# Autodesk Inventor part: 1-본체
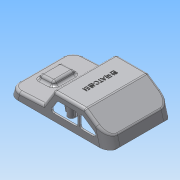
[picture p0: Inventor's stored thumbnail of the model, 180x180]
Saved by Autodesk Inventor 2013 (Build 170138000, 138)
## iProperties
Created: 2015-05
Part Number: 1-본체
Material: ABS 플라스틱
Document SubType Name: Modeling
Designer: Administrator
Density: 7.85 g/cm^3
Mass: 279.283 g
Surface Area: 339.779 cm^2
Volume: 35.5774 cm^3
Author: Administrator
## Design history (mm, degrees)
sketch "스케치1"
  geometry: L1 (-61, -38)-(61, -38); L2 (61, -38)-(61, 38); L3 (61, 38)-(-61, 38); L4 (-61, 38)-(-61, -38); L5 (-61, -38)-(61, 38); L6 (61, -38)-(-61, 38); 1 further point
  constraints: 12 end point, 2 midpoint, 2 parallel, 1 horizontal, 1 perpendicular
  dimensions: "d0" = 122 distance of L2.end L3.end; "d2" = 76 distance of L1.end L2.end
extrude "돌출1" new body sketch "스케치1" distance "d3" = 31; taper "d4" = 0 deg
sketch "스케치2"
  geometry: L1 (0, 0)-(122, 0) reference; L2 (122, 0)-(122, 31) reference; L3 (0, 31)-(122, 31) reference; L4 (0, 0)-(0, 31) reference; L5 (0, 1)-(2.144, 9); L6 (2.144, 9)-(42, 11.089); L7 (92, 31)-(118.833, 12.819); L8 (118.833, 12.819)-(122, 1); L9 (0, 1)-(1, 1); L10 (1, 1)-(1, 0); L11 (122, 1)-(121, 1); L12 (121, 1)-(121, 0); L13 (42, 11.089)-(54.442, 31); L14 (118.833, 12.819)-(122, 11); 1 further point
  constraints: 20 end point, 7 point on line, 4 perpendicular
  dimensions: "d5" = 1 distance of L5.start L9.end; "d7" = 1 distance of L9.end L10.end; "d8" = 105 deg angle of L5 L1; "d9" = 105 deg angle of L8 L1; "d10" = 20 vertical distance of L7.start L14.end; "d11" = 30 horizontal distance of L14.end L7.start; "d12" = 125 deg angle of L13 L6; "d13" = 42 horizontal distance of L6.end L5.start; "d14" = 1 distance of L8.end L11.end; "d15" = 1 distance of L11.end L12.end; "d17" = 9 distance from line of L5.end L1; "d18" = 3 deg angle of L1 L6; "d19" = 60.132 deg angle of L14 L2
extrude "돌출2" sketch "스케치2" distance "d20" = 137.5; taper "d21" = 0 deg
sketch "스케치3"
  geometry: L1 (50, 9.464)-(48.444, 14.553); L2 (48.444, 14.553)-(32.079, 15.41); L3 (32.079, 15.41)-(30, 10.512); L4 (58.856, 9)-(19, 11.089) reference; L5 (61, 1)-(58.856, 9) reference; L6 (60, 0)-(-60, 0) reference; L7 (60, 1)-(61, 1) reference; 2 further points
  constraints: 6 end point, 2 point on line, 1 coincident, 1 parallel
  dimensions: "d25" = 70 deg angle of L3 L4; "d26" = 70 deg angle of L4 L1; "d27" = 11 horizontal distance of point (61, 1) L1.start; "d29" = 20 horizontal distance of L3.end L1.start; "d102" = 5 distance between parallel lines of L2 L4
extrude "돌출3" join sketch "스케치3" stored distance "d30" = 26; taper "d31" = 0 deg
fillet "모깎기1" dims "d32" = 12
fillet "모깎기2" dims "d33" = 3
fillet "모깎기3" dims "d34" = 3
fillet "모깎기4" dims "d35" = 3
feature "쉘1" dims "d36" = 2
sketch "스케치4"
  geometry: L1 (61, 26)-(61, -26) reference; 2 further points
  constraints: 1 horizontal alignment, 1 other
  dimensions: "d37" = 50 distance from line of L1 point (11, 0)
feature "엠보싱1" sketch "스케치4" dims "d5" = 1, "d7" = 1, "d8" = 105 deg, "d9" = 105 deg, "d10" = 20, "d11" = 30, "d12" = 125 deg, "d13" = 42, "d14" = 1, "d15" = 1, "d17" = 9, "d18" = 3 deg, "d19" = 10.49502, "d38" = 0.5, "d39" = 0
sketch "스케치6"
  geometry: L1 (78.924, 28)-(92.685, 18.676) reference; L2 (43.949, 28)-(78.924, 28) reference; L3 (31.561, 8.175)-(43.949, 28) reference; L4 (45.84, 21.59)-(40.216, 12.59); L5 (42.76, 8)-(68.348, 8); L6 (71.348, 11)-(71.348, 20); L7 (68.348, 23)-(48.384, 23); L8 (73.528, 20)-(73.528, 11); L9 (76.528, 8)-(89.752, 8); L10 (76.528, 23)-(77.39, 23); L11 (77.39, 23)-(91.435, 13.484); A1 r 3 centre (42.76, 11) between (40.216, 12.59) and (42.76, 8); A2 r 3 centre (48.384, 20) between (48.384, 23) and (45.84, 21.59); A3 r 3 centre (68.348, 20) between (71.348, 20) and (68.348, 23); A4 r 3 centre (68.348, 11) between (68.348, 8) and (71.348, 11); A5 r 3 centre (89.752, 11) between (89.752, 8) and (91.435, 13.484); A6 r 3 centre (76.528, 11) between (73.528, 11) and (76.528, 8); A7 r 3 centre (76.528, 20) between (76.528, 23) and (73.528, 20); 7 further points
  constraints: 16 end point, 14 point on circle, 14 tangent, 12 point on line, 7 centre point, 5 equal radius, 4 parallel, 4 perpendicular
  dimensions: "d88" = 15 distance of point (71.348, 8) point (71.348, 23); "d90" = 34 distance of point (37.348, 8) point (71.348, 8); "d91" = 5 distance between parallel lines of L3 L4; "d92" = 5 distance between parallel lines of L2 L7; "d93" = 3 radius of A1; "d95" = 26 distance of point (73.528, 8) point (99.528, 8); "d96" = 15 distance of point (73.528, 23) point (73.528, 8); "d97" = 5 distance between parallel lines of L1 L11; "d98" = 5 distance between parallel lines of L2 L10; "d99" = 3 radius of A5
extrude "돌출5" cut sketch "스케치6" stored distance "d100" = 26; taper "d101" = 0 deg
node "작업 평면1"
node "작업 평면2"
sketch "스케치7"
  geometry: A1 r 4 centre (0, 46) between (0, 42) and (0, 50); A2 r 4 centre (0, 35) between (0, 31) and (0, 39); A3 r 4 centre (0, 15) between (0, 11) and (0, 19); A4 r 4 centre (0, 4) between (0, 0) and (0, 8); 2 further points
  constraints: 8 point on circle, 4 centre point, 3 equal radius, 12 other
  dimensions: "d103" = 8 diameter of A1; "d105" = 11 distance of A2.centre A1.centre; "d106" = 20 distance of A3.centre A2.centre; "d107" = 11 distance of A4.centre A3.centre
extrude "돌출6" join sketch "스케치7" distance "d108" = 2; taper "d109" = 0 deg
fillet "모깎기5" dims "d110" = 1
node "작업 평면4"
sketch "스케치14"
  geometry: L1 (46.438, 23)-(48.438, 23); L2 (48.438, 23)-(48.438, 21); L3 (48.438, 21)-(46.438, 21); L4 (46.438, 21)-(46.438, 23); L5 (46.438, 23)-(48.438, 21); L6 (48.438, 23)-(46.438, 21); L7 (31, 23)-(33, 23); L8 (33, 23)-(33, 21); L9 (33, 21)-(31, 21); L10 (31, 21)-(31, 23); L11 (31, 23)-(33, 21); L12 (33, 23)-(31, 21); L13 (58, 30.668)-(58, -30.668) reference; C1 r 4 at (37, 22); 5 further points
  constraints: 24 end point, 6 midpoint, 4 parallel, 4 perpendicular, 2 horizontal, 2 horizontal alignment, 1 centre point, 1 tangent
  dimensions: "d142" = 2 distance of L7.start L7.end; "d144" = 2 distance of L1.start L1.end; "d145" = 4 radius of C1; "d146" = 21 distance from line of C1.centre L13; "d147" = 22 vertical distance of C1.centre point (0, 0)
node "솔리드1"
other parameters: "d141" = -2
